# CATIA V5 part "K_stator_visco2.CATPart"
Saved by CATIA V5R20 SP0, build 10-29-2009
Part number: stator visco2
Bounding box of the stored display mesh (mm): x -170 to 170, y -145 to -85, z -170 to 170
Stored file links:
  G:\Khaled_CFAO_2011\ST2M\ST2M_GR1\mponsin\Khaled\CAD_ThinkMOTION\K_stator_visco2.CATPart
  C:\Users\Socar\Documents\thinkmotion\Final\Diff2.CATProduct
  G:\Khaled_CFAO_2011\ST2M\ST2M_GR1\mponsin\Khaled\CAD_ThinkMOTION\K_mponsin.CATProduct
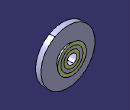
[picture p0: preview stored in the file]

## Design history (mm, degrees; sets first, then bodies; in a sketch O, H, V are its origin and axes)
External parameters (linked from other documents)
  `External.R interface stat_tot` = 50 mm
  `External.Rint embrayage` = 70 mm
  `External.hauteur du visco` = 170 mm
Set1
  Line1 "axe general": linked copy from another document
  DatumSurface1: linked copy from another document
  Plane1 "interface visco/embrayage": linked copy from another document
  DatumSurface2: linked copy from another document
Body1 (main body)
  Sketch1 on yz-plane, origin (0, 0, 0), H (0, 1, 0), V (0, 0, 1)
    line L1 (-145, 170) -> (-110, 170)
    line L2 (-110, 170) -> (-110, 70)
    line L3 (-145, 50) -> (-85, 50)
    line L4 (-85, 50) -> (-85, 70)
    line L5 (-85, 70) -> (-110, 70)
    reference intersected line E1 through (-110, 0) direction (0, 1) from Plane1
    reference projected line E2 through (0, 0) direction (1, 0) from Line1
    reference projected line E3 through (0, 0) direction (1, 0) from Line1
    reference projected line E4 through (0, 0) direction (1, 0) from Line1
    reference intersected line E5 through (-85, 0) direction (0, -1) from face of DatumSurface2
    line L6 (-145, 170) -> (-145, 50)
    reference intersected line E6 through (-145, 0) direction (0, 1) from DatumSurface1
    distance L1 E2 = 170 {= `External.hauteur du visco`}
    distance L3 E3 = 50 {= `External.R interface stat_tot`}
    distance L5 E4 = 70 {= `External.Rint embrayage`}
    horizontal: L1 H, L3 H, L5 H
    vertical: L2 V, L4 V, L6 V
    coincidence: E1 L2, L4 E5, L6 E6
  Shaft1: profile Sketch1, axis Line1, angle 360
